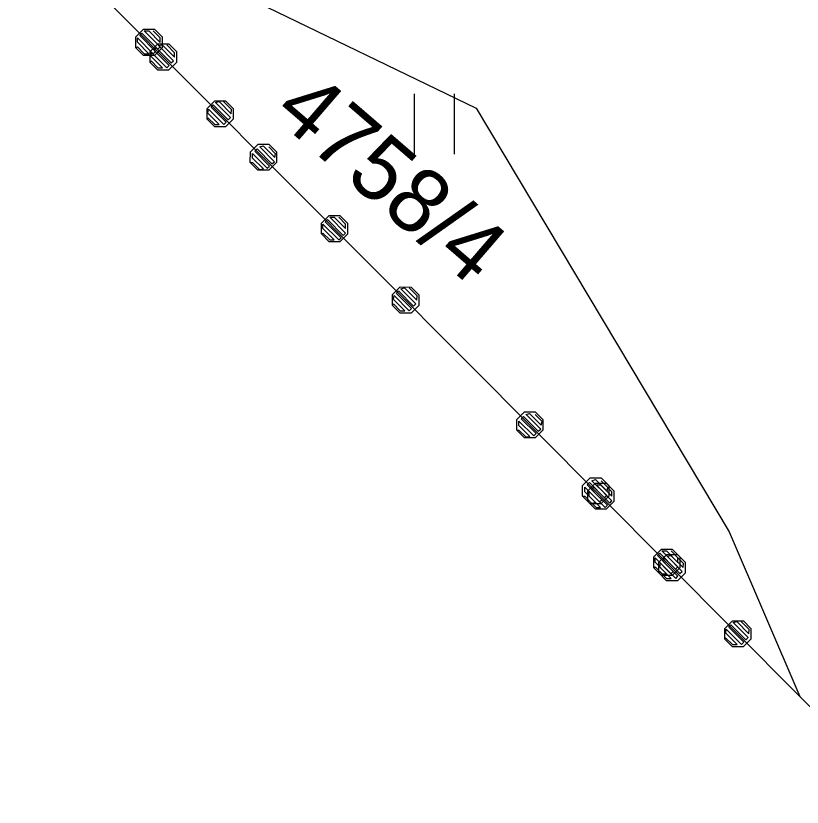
# Model space of a CAD drawing. Extents: x -266179 to -264727, y -1243225 to -1241702.
# Drawn here: x -266045.74 to -266026.16, y -1242747.95 to -1242728.24 of the extents above; entities that cross this region are included whole.
import ezdxf

# ---------------------------------------------------------------- set-up
doc = ezdxf.new("R2010")
doc.units = 0
for name, color, linetype in [('Vrstva 1', 7, 'Continuous'), ('Vrstva 19', 7, 'Continuous'), ('Vrstva 21', 7, 'Continuous')]:
    doc.layers.add(name, color=color, linetype=linetype)

msp = doc.modelspace()

# ---------------------------------------------------------------- linework, layer by layer
at = {"layer": 'Vrstva 1'}
for p, q in [((-266034.49, -1242736.88), (-266045.74, -1242725.58)), ((-266041.37, -1242727.11), (-266034.28, -1242730.54)), ((-266035.82, -1242730.19), (-266035.82, -1242731.69)), ((-266034.82, -1242731.69), (-266034.82, -1242730.19)), ((-266034.28, -1242730.54), (-266027.98, -1242741.09)), ((-266026.22, -1242745.19), (-266034.49, -1242736.88)), ((-266027.98, -1242741.09), (-266026.22, -1242745.19)), ((-266020.7, -1242750.74), (-266026.22, -1242745.19))]:
    msp.add_line(p, q, dxfattribs=at)
at = {"layer": 'Vrstva 19'}
for p, q in [((-266034.49, -1242736.88), (-266045.74, -1242725.58)), ((-266026.22, -1242745.19), (-266034.49, -1242736.88)), ((-266020.7, -1242750.74), (-266026.22, -1242745.19))]:
    msp.add_line(p, q, dxfattribs=at)
for points in [[(-266042.75, -1242729.037), (-266042.749, -1242728.769), (-266042.558, -1242728.578), (-266042.289, -1242728.579), (-266042.098, -1242728.77), (-266042.099, -1242729.039), (-266042.29, -1242729.229), (-266042.559, -1242729.229), (-266042.75, -1242729.037), (-266042.714, -1242729.016), (-266042.545, -1242729.186), (-266042.432, -1242729.187), (-266042.714, -1242728.903), (-266042.714, -1242728.79), (-266042.319, -1242729.187), (-266042.262, -1242729.13), (-266042.657, -1242728.733), (-266042.6, -1242728.677), (-266042.205, -1242729.074), (-266042.148, -1242729.017), (-266042.544, -1242728.621), (-266042.43, -1242728.621), (-266042.148, -1242728.904), (-266042.148, -1242728.791), (-266042.317, -1242728.621)], [(-266042.395, -1242729.402), (-266042.394, -1242729.133), (-266042.202, -1242728.943), (-266041.934, -1242728.944), (-266041.743, -1242729.135), (-266041.744, -1242729.404), (-266041.936, -1242729.594), (-266042.205, -1242729.593), (-266042.395, -1242729.402), (-266042.374, -1242729.367), (-266042.204, -1242729.537), (-266042.091, -1242729.537), (-266042.373, -1242729.253), (-266042.359, -1242729.154), (-266041.978, -1242729.538), (-266041.921, -1242729.481), (-266042.295, -1242729.105), (-266042.245, -1242729.042), (-266041.872, -1242729.418), (-266041.815, -1242729.361), (-266042.188, -1242728.985), (-266042.096, -1242728.964), (-266041.793, -1242729.269), (-266041.786, -1242729.163), (-266041.983, -1242728.965)], [(-266040.979, -1242730.816), (-266040.978, -1242730.547), (-266040.787, -1242730.357), (-266040.518, -1242730.357), (-266040.327, -1242730.549), (-266040.328, -1242730.817), (-266040.519, -1242731.008), (-266040.788, -1242731.007), (-266040.979, -1242730.816), (-266040.957, -1242730.781), (-266040.788, -1242730.951), (-266040.675, -1242730.951), (-266040.957, -1242730.668), (-266040.943, -1242730.569), (-266040.562, -1242730.951), (-266040.505, -1242730.895), (-266040.879, -1242730.519), (-266040.829, -1242730.456), (-266040.455, -1242730.831), (-266040.399, -1242730.775), (-266040.773, -1242730.399), (-266040.681, -1242730.378), (-266040.377, -1242730.683), (-266040.37, -1242730.577), (-266040.568, -1242730.379)], [(-266039.903, -1242731.897), (-266039.902, -1242731.628), (-266039.711, -1242731.438), (-266039.442, -1242731.438), (-266039.251, -1242731.63), (-266039.252, -1242731.899), (-266039.443, -1242732.089), (-266039.712, -1242732.088), (-266039.903, -1242731.897), (-266039.846, -1242731.897), (-266039.677, -1242732.067), (-266039.578, -1242732.053), (-266039.846, -1242731.784), (-266039.845, -1242731.671), (-266039.479, -1242732.039), (-266039.422, -1242731.983), (-266039.789, -1242731.614), (-266039.732, -1242731.558), (-266039.365, -1242731.927), (-266039.301, -1242731.877), (-266039.668, -1242731.509), (-266039.583, -1242731.481), (-266039.294, -1242731.771), (-266039.273, -1242731.679), (-266039.442, -1242731.509)], [(-266038.132, -1242733.676), (-266038.131, -1242733.407), (-266037.94, -1242733.217), (-266037.671, -1242733.217), (-266037.48, -1242733.409), (-266037.481, -1242733.677), (-266037.672, -1242733.868), (-266037.941, -1242733.867), (-266038.132, -1242733.676), (-266038.096, -1242733.655), (-266037.927, -1242733.825), (-266037.814, -1242733.825), (-266038.096, -1242733.542), (-266038.096, -1242733.428), (-266037.701, -1242733.825), (-266037.644, -1242733.769), (-266038.039, -1242733.372), (-266037.982, -1242733.316), (-266037.587, -1242733.712), (-266037.53, -1242733.656), (-266037.926, -1242733.259), (-266037.812, -1242733.259), (-266037.53, -1242733.543), (-266037.53, -1242733.43), (-266037.699, -1242733.26)], [(-266036.361, -1242735.455), (-266036.36, -1242735.186), (-266036.169, -1242734.995), (-266035.9, -1242734.996), (-266035.71, -1242735.187), (-266035.71, -1242735.456), (-266035.901, -1242735.646), (-266036.17, -1242735.646), (-266036.361, -1242735.455), (-266036.339, -1242735.419), (-266036.17, -1242735.589), (-266036.057, -1242735.59), (-266036.339, -1242735.306), (-266036.325, -1242735.207), (-266035.944, -1242735.59), (-266035.887, -1242735.533), (-266036.261, -1242735.158), (-266036.211, -1242735.094), (-266035.837, -1242735.47), (-266035.781, -1242735.413), (-266036.155, -1242735.038), (-266036.063, -1242735.017), (-266035.759, -1242735.322), (-266035.752, -1242735.215), (-266035.95, -1242735.017)], [(-266033.271, -1242738.559), (-266033.271, -1242738.291), (-266033.079, -1242738.1), (-266032.81, -1242738.101), (-266032.62, -1242738.292), (-266032.621, -1242738.561), (-266032.812, -1242738.751), (-266033.081, -1242738.751), (-266033.271, -1242738.559), (-266033.215, -1242738.559), (-266033.045, -1242738.729), (-266032.946, -1242738.716), (-266033.214, -1242738.446), (-266033.214, -1242738.333), (-266032.847, -1242738.702), (-266032.79, -1242738.645), (-266033.157, -1242738.277), (-266033.101, -1242738.22), (-266032.734, -1242738.589), (-266032.67, -1242738.539), (-266033.037, -1242738.171), (-266032.952, -1242738.143), (-266032.663, -1242738.433), (-266032.641, -1242738.341), (-266032.811, -1242738.171)], [(-266031.632, -1242740.206), (-266031.631, -1242739.938), (-266031.44, -1242739.747), (-266031.171, -1242739.748), (-266030.981, -1242739.939), (-266030.981, -1242740.208), (-266031.173, -1242740.398), (-266031.441, -1242740.398), (-266031.632, -1242740.206), (-266031.575, -1242740.207), (-266031.406, -1242740.377), (-266031.307, -1242740.363), (-266031.575, -1242740.093), (-266031.575, -1242739.98), (-266031.208, -1242740.349), (-266031.151, -1242740.292), (-266031.518, -1242739.924), (-266031.461, -1242739.867), (-266031.095, -1242740.236), (-266031.031, -1242740.187), (-266031.398, -1242739.818), (-266031.313, -1242739.79), (-266031.023, -1242740.08), (-266031.002, -1242739.989), (-266031.171, -1242739.819)], [(-266031.5, -1242740.338), (-266031.5, -1242740.069), (-266031.308, -1242739.879), (-266031.04, -1242739.879), (-266030.849, -1242740.071), (-266030.85, -1242740.339), (-266031.041, -1242740.53), (-266031.31, -1242740.529), (-266031.5, -1242740.338), (-266031.465, -1242740.317), (-266031.295, -1242740.487), (-266031.182, -1242740.487), (-266031.465, -1242740.204), (-266031.464, -1242740.091), (-266031.069, -1242740.487), (-266031.012, -1242740.431), (-266031.408, -1242740.034), (-266031.351, -1242739.978), (-266030.956, -1242740.375), (-266030.899, -1242740.318), (-266031.294, -1242739.921), (-266031.181, -1242739.921), (-266030.899, -1242740.205), (-266030.899, -1242740.092), (-266031.068, -1242739.922)], [(-266029.861, -1242741.985), (-266029.86, -1242741.716), (-266029.669, -1242741.526), (-266029.4, -1242741.527), (-266029.21, -1242741.718), (-266029.21, -1242741.987), (-266029.402, -1242742.177), (-266029.67, -1242742.176), (-266029.861, -1242741.985), (-266029.826, -1242741.964), (-266029.656, -1242742.134), (-266029.543, -1242742.134), (-266029.825, -1242741.851), (-266029.825, -1242741.738), (-266029.43, -1242742.135), (-266029.373, -1242742.078), (-266029.768, -1242741.681), (-266029.712, -1242741.625), (-266029.317, -1242742.022), (-266029.26, -1242741.965), (-266029.655, -1242741.568), (-266029.542, -1242741.569), (-266029.26, -1242741.852), (-266029.259, -1242741.739), (-266029.429, -1242741.569)], [(-266029.729, -1242742.117), (-266029.729, -1242741.848), (-266029.537, -1242741.658), (-266029.269, -1242741.658), (-266029.078, -1242741.849), (-266029.079, -1242742.118), (-266029.27, -1242742.309), (-266029.539, -1242742.308), (-266029.729, -1242742.117), (-266029.708, -1242742.081), (-266029.539, -1242742.251), (-266029.425, -1242742.252), (-266029.708, -1242741.968), (-266029.693, -1242741.869), (-266029.312, -1242742.252), (-266029.256, -1242742.196), (-266029.63, -1242741.82), (-266029.58, -1242741.756), (-266029.206, -1242742.132), (-266029.149, -1242742.076), (-266029.523, -1242741.7), (-266029.431, -1242741.679), (-266029.128, -1242741.984), (-266029.121, -1242741.878), (-266029.318, -1242741.679)], [(-266028.09, -1242743.764), (-266028.089, -1242743.495), (-266027.898, -1242743.305), (-266027.629, -1242743.305), (-266027.439, -1242743.497), (-266027.439, -1242743.765), (-266027.631, -1242743.956), (-266027.899, -1242743.955), (-266028.09, -1242743.764), (-266028.069, -1242743.729), (-266027.899, -1242743.899), (-266027.786, -1242743.899), (-266028.068, -1242743.615), (-266028.054, -1242743.516), (-266027.673, -1242743.899), (-266027.616, -1242743.843), (-266027.99, -1242743.467), (-266027.941, -1242743.404), (-266027.567, -1242743.779), (-266027.51, -1242743.723), (-266027.884, -1242743.347), (-266027.792, -1242743.326), (-266027.489, -1242743.631), (-266027.481, -1242743.525), (-266027.679, -1242743.326)]]:
    msp.add_lwpolyline(points, dxfattribs=at)
at = {"layer": 'Vrstva 21'}
for p, q in [((-266034.49, -1242736.88), (-266045.74, -1242725.58)), ((-266026.22, -1242745.19), (-266034.49, -1242736.88)), ((-266020.7, -1242750.74), (-266026.22, -1242745.19))]:
    msp.add_line(p, q, dxfattribs=at)

# ---------------------------------------------------------------- texts
at = {"layer": 'Vrstva 1'}
msp.add_text('4758/4', height=1.6, rotation=319.2521, dxfattribs=at).set_placement((-266039.38, -1242730.727))

doc.saveas('drawing.dxf')
